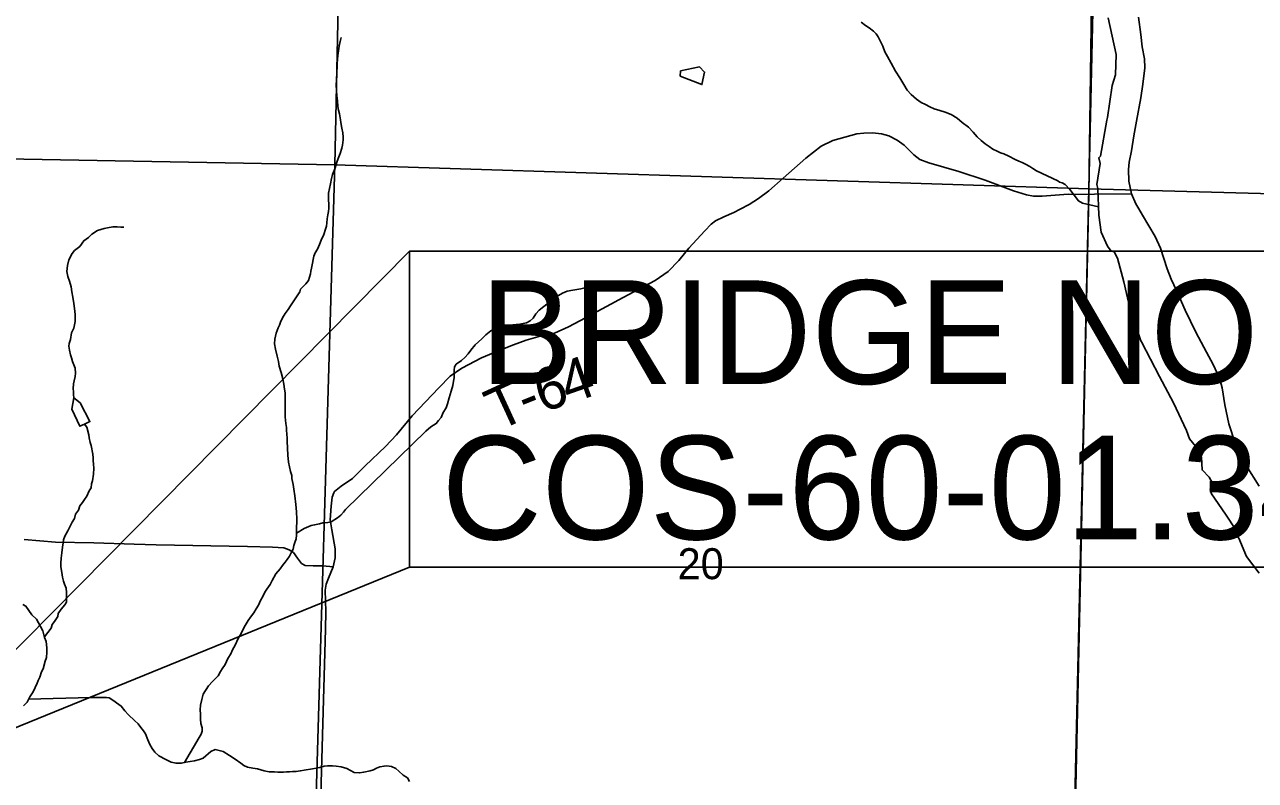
# Model space of a CAD drawing. Extents: x 0 to 34, y 0 to 22.
# Drawn here: x 5.636 to 7.298, y 17.548 to 18.569 of the extents above; entities that cross this region are included whole.
import ezdxf

# ---------------------------------------------------------------- set-up
doc = ezdxf.new("R2010")
doc.units = 0
for name, color, linetype in [('GM_X_Corporation', 7, 'Continuous'), ('GM_X_County_Road', 7, 'Continuous'), ('GM_X_Minor_Lake', 7, 'Continuous'), ('GM_X_Minor_River', 7, 'Continuous'), ('GM_X_Section_Text', 7, 'Continuous'), ('GM_X_Township_Road', 7, 'Continuous'), ('GM_X_Township_Road_Text', 7, 'Continuous'), ('SH_Text', 7, 'Continuous')]:
    doc.layers.add(name, color=color, linetype=linetype)

msp = doc.modelspace()

# ---------------------------------------------------------------- linework, layer by layer
at = {"layer": 'GM_X_Corporation'}
msp.add_lwpolyline([(4.9914, 16.3477), (5.6931, 16.3352), (5.9938, 16.3204), (6.9309, 16.303), (7.0302, 16.2995), (7.0306, 16.367), (7.0337, 16.3927), (7.0334, 16.423), (7.0339, 16.4517), (7.0342, 16.5147), (7.0361, 16.5712), (7.0442, 17.0463), (7.0729, 18.3402), (7.0876, 19.4092), (7.1008, 19.81), (7.1249, 20.7061), (7.1302, 20.9), (2.2795, 20.9)], dxfattribs=at)
for points in [[(8.9, 16.2485), (8.9, 20.9), (7.1302, 20.9), (7.1249, 20.7061), (7.1008, 19.81), (7.0876, 19.4092), (7.0729, 18.3402), (7.0442, 17.0463), (7.0361, 16.5712), (7.0342, 16.5147), (7.0339, 16.4517), (7.0334, 16.423), (7.0337, 16.3927), (7.0306, 16.367), (7.0302, 16.2995), (7.0491, 16.2993), (8.0233, 16.275), (8.785, 16.2515)], [(5.0447, 19.4257), (6.0762, 19.405), (6.0547, 18.3798), (5.0167, 18.3983)], [(6.0762, 19.405), (7.0925, 19.3811), (7.0882, 19.1112), (7.0832, 18.8066), (7.0725, 18.3472), (6.0547, 18.3798)], [(7.0832, 18.8066), (7.5969, 18.8015), (8.1004, 18.7963), (8.0825, 18.3198), (7.0725, 18.3472)], [(5.0167, 18.3983), (6.0547, 18.3798), (6.0244, 17.3604), (4.9971, 17.3675)], [(7.0725, 18.3472), (7.0493, 17.3262), (6.0244, 17.3604), (6.0547, 18.3798)], [(7.0725, 18.3472), (8.0825, 18.3198), (8.0536, 17.3026), (7.0493, 17.3262)]]:
    msp.add_lwpolyline(points, close=True, dxfattribs=at)
at = {"layer": 'GM_X_County_Road'}
for points in [[(6.0524, 17.8366), (6.0383, 17.8378), (6.0255, 17.8378), (6.0147, 17.8382), (6.0098, 17.8409), (6.0044, 17.8482), (5.9988, 17.8558), (5.9928, 17.8597), (5.9856, 17.8622), (5.9707, 17.863), (5.9367, 17.8641), (5.8136, 17.8662), (5.7836, 17.867), (5.7294, 17.8688), (5.6775, 17.8697), (5.6353, 17.8736)], [(6.033, 17.3642), (6.0307, 17.371), (6.0314, 17.3933), (6.0345, 17.4804), (6.0385, 17.6249), (6.0421, 17.7526), (6.0425, 17.7762), (6.0418, 17.8051), (6.0431, 17.8132), (6.0462, 17.8213), (6.0524, 17.8366)]]:
    msp.add_lwpolyline(points, dxfattribs=at)
at = {"layer": 'GM_X_Minor_Lake'}
for points in [[(6.521, 18.4996), (6.5502, 18.4879), (6.5539, 18.505), (6.5471, 18.5118)], [(6.5471, 18.5118), (6.5214, 18.5065), (6.521, 18.4996)], [(5.7024, 18.0647), (5.6994, 18.0495), (5.7104, 18.0264), (5.7169, 18.0295)], [(5.7169, 18.0295), (5.7241, 18.0329), (5.7107, 18.0583), (5.7024, 18.0647)]]:
    msp.add_lwpolyline(points, dxfattribs=at)
at = {"layer": 'GM_X_Minor_River'}
for points in [[(7.3025, 17.828), (7.2855, 17.8504), (7.2754, 17.8754), (7.2735, 17.8777), (7.2712, 17.8868), (7.2573, 17.9077), (7.2385, 17.9354), (7.2366, 17.9411), (7.2396, 17.9498), (7.2351, 17.9578), (7.2257, 17.9676), (7.225, 17.9847), (7.2167, 17.9998), (7.2084, 18.0093), (7.2046, 18.0207), (7.187, 18.0583), (7.1681, 18.0939), (7.144, 18.1406), (7.1429, 18.1417), (7.1283, 18.1842), (7.12, 18.2217), (7.1114, 18.2535), (7.1069, 18.2622), (7.1027, 18.263), (7.0978, 18.2698), (7.0892, 18.2888), (7.0862, 18.3115), (7.0848, 18.3475), (7.0833, 18.3532), (7.0879, 18.3812), (7.086, 18.3892), (7.0883, 18.3911), (7.0971, 18.4399), (7.0979, 18.4437), (7.1044, 18.4868), (7.1086, 18.5012), (7.1094, 18.5285), (7.099, 18.5781)], [(7.0308, 18.3578), (7.0019, 18.3717), (6.997, 18.3747), (6.9932, 18.3774), (6.9871, 18.3804), (6.9829, 18.3827), (6.978, 18.3846), (6.973, 18.3868), (6.9647, 18.3914), (6.9579, 18.3944), (6.9533, 18.3959), (6.9488, 18.3981), (6.9431, 18.4008), (6.9381, 18.4042), (6.9328, 18.408), (6.9275, 18.4125), (6.9218, 18.4174), (6.9165, 18.4239), (6.91, 18.4303), (6.9016, 18.4367), (6.8948, 18.4428), (6.8868, 18.4477), (6.8785, 18.4507), (6.8713, 18.453), (6.8637, 18.4552), (6.858, 18.4579), (6.8523, 18.4609), (6.8462, 18.4639), (6.8398, 18.4681), (6.8326, 18.4745), (6.8276, 18.4805), (6.8227, 18.4881), (6.8173, 18.4972), (6.8116, 18.5063), (6.8059, 18.5169), (6.8009, 18.526), (6.7971, 18.5324), (6.7945, 18.54), (6.7914, 18.5464), (6.7884, 18.5525), (6.7857, 18.5566), (6.7819, 18.5601), (6.7762, 18.5646), (6.7713, 18.568), (6.7652, 18.5725)], [(6.0231, 18.2401), (6.0243, 18.2469), (6.0254, 18.2519), (6.0265, 18.2564), (6.028, 18.2606), (6.0314, 18.2659), (6.034, 18.272), (6.0363, 18.2777), (6.0397, 18.2853), (6.0423, 18.2925), (6.0434, 18.2966), (6.0438, 18.3012), (6.0445, 18.3065), (6.0453, 18.3122), (6.046, 18.3167), (6.0464, 18.3209), (6.0467, 18.3258), (6.046, 18.3334), (6.0463, 18.3414), (6.0489, 18.3539), (6.0504, 18.3611), (6.0515, 18.3664), (6.0545, 18.3744), (6.0579, 18.3846), (6.0602, 18.3903), (6.0621, 18.3949), (6.0643, 18.4021), (6.0651, 18.4062), (6.0658, 18.4134), (6.0658, 18.4172), (6.0654, 18.4229), (6.0642, 18.429), (6.0627, 18.4366), (6.0623, 18.4403), (6.0611, 18.4483), (6.0596, 18.4536), (6.0588, 18.4585), (6.0584, 18.4661), (6.0573, 18.4726), (6.0565, 18.487), (6.0568, 18.4938), (6.0576, 18.5044), (6.0579, 18.5127), (6.0579, 18.5169), (6.0586, 18.5275), (6.0605, 18.54), (6.062, 18.5461), (6.0631, 18.5514)], [(7.0858, 18.323), (7.0643, 18.3279), (7.0587, 18.3309), (7.047, 18.3461), (7.0406, 18.353), (7.0367, 18.3555), (7.035, 18.3558), (7.0331, 18.3564), (7.0308, 18.3578)], [(5.7024, 18.0647), (5.702, 18.0693), (5.7019, 18.0734), (5.7016, 18.0772), (5.7019, 18.084), (5.7027, 18.0878), (5.7042, 18.0935), (5.7045, 18.0981), (5.7041, 18.1049), (5.7007, 18.114), (5.6992, 18.1189), (5.698, 18.1231), (5.6965, 18.1291), (5.6957, 18.1345), (5.6961, 18.1382), (5.6976, 18.1439), (5.699, 18.1527), (5.7021, 18.1591), (5.7032, 18.1637), (5.7039, 18.1678), (5.7039, 18.1773), (5.7031, 18.1856), (5.7023, 18.1921), (5.7008, 18.2008), (5.6996, 18.208), (5.6989, 18.2148), (5.6966, 18.2224), (5.6943, 18.2288), (5.6927, 18.2357), (5.6938, 18.2436), (5.6957, 18.2512), (5.6999, 18.2599), (5.7032, 18.2637), (5.7104, 18.2694), (5.7157, 18.277), (5.7221, 18.2816), (5.7267, 18.2861), (5.7342, 18.2907), (5.7433, 18.2934), (5.7479, 18.2945), (5.7551, 18.2957), (5.7607, 18.2957), (5.7657, 18.2953), (5.7698, 18.2953)], [(5.8518, 17.5722), (5.8716, 17.606), (5.8743, 17.6105), (5.8754, 17.6147), (5.8754, 17.6192), (5.8739, 17.6249), (5.8735, 17.631), (5.8731, 17.6374), (5.873, 17.6435), (5.8734, 17.6499), (5.8749, 17.6572), (5.8771, 17.6644), (5.8839, 17.6757), (5.8896, 17.6818), (5.8971, 17.6894), (5.9005, 17.6951), (5.9024, 17.6989), (5.9066, 17.7046), (5.9103, 17.7126), (5.9141, 17.719), (5.9167, 17.7243), (5.9201, 17.7308), (5.9243, 17.7399), (5.9284, 17.7464), (5.9322, 17.7551), (5.9375, 17.7642), (5.9409, 17.7688), (5.9454, 17.7745), (5.9484, 17.7798), (5.9518, 17.7847), (5.9544, 17.7912), (5.9574, 17.7965), (5.9601, 17.8022), (5.9627, 17.8063), (5.9673, 17.8128), (5.9699, 17.8181), (5.9748, 17.8272), (5.9808, 17.834), (5.9842, 17.8386), (5.9876, 17.8428), (5.9903, 17.8466), (5.9933, 17.8508), (5.9963, 17.8564), (5.9982, 17.8606), (5.9993, 17.8652), (6.0008, 17.8693), (6.0023, 17.8743), (6.0027, 17.8796), (6.003, 17.8853), (6.003, 17.891), (6.0034, 17.8959), (6.0034, 17.9012), (6.0029, 17.9107), (6.0022, 17.9209), (6.0006, 17.9323), (5.9991, 17.9417), (5.9983, 17.9478), (5.9964, 17.9561), (5.9964, 17.9599), (5.9948, 17.9656), (5.9933, 17.9717), (5.9921, 17.9781), (5.991, 17.9876), (5.9906, 17.9971), (5.9905, 18.0065), (5.9901, 18.0103), (5.9893, 18.021), (5.9893, 18.0247), (5.9886, 18.03), (5.9878, 18.0391), (5.9874, 18.0448), (5.9874, 18.052), (5.9877, 18.0581), (5.9877, 18.0717), (5.9869, 18.0767), (5.9857, 18.0835), (5.9846, 18.0907), (5.9823, 18.099), (5.9796, 18.1077), (5.9788, 18.1138), (5.9769, 18.121), (5.9746, 18.1305), (5.9731, 18.1377), (5.9738, 18.1441), (5.9753, 18.1521), (5.9783, 18.1593), (5.9798, 18.1631), (5.9813, 18.1673), (5.9839, 18.1729), (5.9877, 18.1786), (5.9915, 18.184), (5.9949, 18.1893), (5.9994, 18.1961), (6.0028, 18.2014), (6.0073, 18.2079), (6.0084, 18.2117), (6.0156, 18.2189), (6.019, 18.2234), (6.0216, 18.2322), (6.0224, 18.2359), (6.0231, 18.2401)], [(6.0028, 17.8819), (6.0132, 17.8883), (6.0227, 17.8925), (6.0273, 17.8933), (6.0341, 17.8948), (6.0386, 17.896), (6.0454, 17.8967), (6.0496, 17.8975), (6.0583, 17.9028), (6.0628, 17.9066), (6.0662, 17.9104), (6.0692, 17.9142), (6.1777, 18.0198), (6.1841, 18.0255), (6.1917, 18.0301), (6.1947, 18.0343), (6.1981, 18.0381), (6.2011, 18.0449), (6.2052, 18.0513), (6.2067, 18.0567), (6.209, 18.065), (6.2116, 18.0737), (6.2139, 18.0817), (6.215, 18.0874), (6.2157, 18.0919), (6.2157, 18.1022), (6.2161, 18.1067), (6.2187, 18.1105), (6.2259, 18.1154), (6.23, 18.1192), (6.2346, 18.1242), (6.2383, 18.1291), (6.244, 18.1363), (6.2531, 18.1447), (6.2584, 18.15), (6.2652, 18.1553), (6.2716, 18.1587), (6.2792, 18.1614), (6.286, 18.1629), (6.2901, 18.163), (6.3045, 18.1645), (6.3091, 18.1653), (6.3133, 18.1664), (6.3186, 18.1687), (6.3223, 18.1725), (6.3261, 18.1782), (6.3306, 18.1831), (6.3367, 18.1881), (6.3408, 18.1915), (6.345, 18.1953), (6.3499, 18.1991), (6.3567, 18.2033), (6.362, 18.2063), (6.3684, 18.209), (6.376, 18.2101), (6.3866, 18.212), (6.3957, 18.2143), (6.4037, 18.2155), (6.4116, 18.2185), (6.4177, 18.2204)], [(5.6626, 17.7419), (5.6715, 17.7538), (5.673, 17.7587), (5.6764, 17.7629), (5.6805, 17.7697), (5.6813, 17.7735), (5.685, 17.7792), (5.6903, 17.7853), (5.6926, 17.7891), (5.6926, 17.802), (5.6918, 17.808), (5.6895, 17.8133), (5.6883, 17.8171), (5.6872, 17.8228), (5.686, 17.8289), (5.6849, 17.8368), (5.6849, 17.8414), (5.6852, 17.8482), (5.686, 17.8554), (5.6871, 17.863), (5.6878, 17.8691), (5.6885, 17.8732), (5.69, 17.8782), (5.6942, 17.8854), (5.6968, 17.8907), (5.7002, 17.8968), (5.7032, 17.9021), (5.7047, 17.9078), (5.7085, 17.9131), (5.7104, 17.9188), (5.7142, 17.9237), (5.7168, 17.9275), (5.7198, 17.9321), (5.7228, 17.9393), (5.7255, 17.9435), (5.7262, 17.9488), (5.7273, 17.9526), (5.7288, 17.962), (5.7292, 17.97), (5.7288, 17.9753), (5.7284, 17.9802), (5.7284, 17.984), (5.728, 17.9886), (5.7257, 18.0003), (5.7245, 18.0045), (5.723, 18.0109), (5.7226, 18.0147), (5.7199, 18.0253), (5.7169, 18.0295)], [(5.6335, 17.7859), (5.6377, 17.7837), (5.6457, 17.7719), (5.6517, 17.7659), (5.6571, 17.756), (5.6605, 17.75), (5.6628, 17.7413), (5.6651, 17.7356), (5.6659, 17.7272), (5.6659, 17.7215), (5.6655, 17.714), (5.6637, 17.709), (5.661, 17.6988), (5.6588, 17.695), (5.6562, 17.6874), (5.6543, 17.6832), (5.6528, 17.6794), (5.6475, 17.6677), (5.643, 17.6612), (5.6392, 17.6536), (5.6343, 17.6487)], [(5.6412, 17.6577), (5.7248, 17.6599), (5.7339, 17.6599), (5.7385, 17.6603), (5.7423, 17.6603), (5.7464, 17.6599), (5.7502, 17.6595), (5.7563, 17.6558), (5.7601, 17.6527), (5.7662, 17.6486), (5.7711, 17.6421), (5.7761, 17.6368), (5.7844, 17.6289), (5.789, 17.6244), (5.7928, 17.6198), (5.7962, 17.6149), (5.7989, 17.6111), (5.8023, 17.6028), (5.805, 17.5967), (5.808, 17.5914), (5.8118, 17.5861), (5.8171, 17.5812), (5.8263, 17.5763), (5.8338, 17.5729), (5.8403, 17.5714), (5.8475, 17.5714), (5.8535, 17.5726), (5.8653, 17.5745), (5.8721, 17.5764), (5.877, 17.5783), (5.8872, 17.587), (5.8929, 17.5897), (5.9039, 17.5871), (5.9126, 17.5818), (5.9202, 17.5769), (5.9278, 17.5712), (5.932, 17.5682), (5.9366, 17.5659), (5.9438, 17.5648), (5.9502, 17.5637), (5.9593, 17.561), (5.9658, 17.5599), (5.9733, 17.5595), (5.9775, 17.5592), (5.9817, 17.5592), (5.9855, 17.5592), (5.9892, 17.5596), (5.9934, 17.5596), (5.9976, 17.56), (6.0021, 17.56), (6.0082, 17.5611), (6.0131, 17.5619), (6.0245, 17.5638), (6.0343, 17.5657), (6.0404, 17.5673), (6.0449, 17.5677), (6.0517, 17.5677), (6.0567, 17.5673), (6.0631, 17.5666), (6.0711, 17.5643), (6.076, 17.5617), (6.0806, 17.559), (6.0882, 17.5583), (6.0938, 17.5594), (6.1022, 17.5609), (6.1067, 17.5625), (6.1109, 17.5648), (6.1154, 17.5663), (6.1211, 17.5674), (6.1249, 17.5678), (6.1313, 17.5667), (6.137, 17.5641), (6.1412, 17.5606), (6.1469, 17.555), (6.1526, 17.5516), (6.1556, 17.5467)]]:
    msp.add_lwpolyline(points, dxfattribs=at)
at = {"layer": 'GM_X_Township_Road'}
msp.add_line((7.0802, 18.3398), (7.1304, 18.3405), dxfattribs=at)
for points in [[(7.1402, 18.3202), (7.136, 18.3269), (7.1304, 18.3405), (7.1267, 18.3577), (7.1261, 18.3732), (7.1271, 18.3831), (7.1303, 18.3983), (7.1334, 18.4187), (7.1371, 18.4388), (7.1427, 18.4701), (7.1455, 18.4887), (7.1482, 18.5105), (7.1477, 18.5227), (7.1448, 18.5392), (7.1427, 18.5558), (7.1398, 18.5791)], [(6.0535, 17.9364), (6.0542, 17.9384), (6.0633, 17.9454), (6.0785, 17.9557), (6.0958, 17.9731), (6.1229, 17.999), (6.1378, 18.0147), (6.1593, 18.0406), (6.1953, 18.0784), (6.2106, 18.0941), (6.226, 18.1049), (6.2529, 18.1188), (6.2744, 18.1277), (6.2961, 18.1365), (6.3128, 18.143), (6.3317, 18.1481), (6.3513, 18.1521), (6.3701, 18.1608), (6.3933, 18.173), (6.4438, 18.2005), (6.487, 18.2232), (6.5046, 18.2354), (6.5193, 18.2503), (6.5328, 18.2671), (6.5541, 18.2905), (6.5628, 18.2996), (6.5688, 18.3039), (6.5799, 18.3095), (6.5936, 18.3153), (6.6021, 18.3198), (6.6139, 18.3261), (6.6267, 18.3341), (6.6405, 18.3443), (6.66, 18.3618), (6.6906, 18.3887), (6.7111, 18.4047), (6.7272, 18.4123), (6.7593, 18.4214), (6.769, 18.4225), (6.7804, 18.4229), (6.7926, 18.4216), (6.8025, 18.4189), (6.8139, 18.4131), (6.8232, 18.4061), (6.8317, 18.3978), (6.8365, 18.3929), (6.8445, 18.3867), (6.8565, 18.3821), (6.8973, 18.3705), (6.9329, 18.3589), (6.9709, 18.3447), (6.9885, 18.3393), (6.9982, 18.3372), (7.0098, 18.3374), (7.0448, 18.3399), (7.0731, 18.3397), (7.0802, 18.3398)], [(7.3028, 17.9456), (7.285, 17.9733), (7.2763, 17.9893), (7.2701, 18.0035), (7.2618, 18.0296), (7.2564, 18.0555), (7.2527, 18.0784), (7.249, 18.0914), (7.2405, 18.1097), (7.2314, 18.1264), (7.2173, 18.1537), (7.2026, 18.1833), (7.191, 18.2098), (7.184, 18.2251), (7.1785, 18.2391), (7.1695, 18.2671), (7.1623, 18.2828), (7.1453, 18.3118), (7.1402, 18.3202)], [(6.0524, 17.8366), (6.0551, 17.8486), (6.0553, 17.8608), (6.0505, 17.8868), (6.0485, 17.9001), (6.0499, 17.9187), (6.0513, 17.9305), (6.0535, 17.9364)]]:
    msp.add_lwpolyline(points, dxfattribs=at)
at = {"layer": 'SH_Text'}
for points in [[(5.4492, 17.5486), (6.1555, 17.8363), (6.1555, 18.2631)], [(6.1555, 18.2631), (7.474, 18.2631), (7.474, 17.8363), (6.1555, 17.8363)]]:
    msp.add_lwpolyline(points, close=True, dxfattribs=at)

# ---------------------------------------------------------------- texts
at = {"layer": 'GM_X_Section_Text'}
msp.add_text('20', height=0.04186, rotation=0, dxfattribs=at).set_placement((6.5175, 17.8199))
at = {"layer": 'GM_X_Township_Road_Text'}
for s, rotation, p in [('4', 19.2895, (6.3702, 18.0559)), ('6', 16.1255, (6.3333, 18.0451)), ('T', 24.6883, (6.2751, 18.0194)), ('-', 21.8753, (6.3131, 18.0369))]:
    msp.add_text(s, height=0.0568, rotation=rotation, dxfattribs=at).set_placement(p)
at = {"layer": 'SH_Text'}
for s, p in [(' BRIDGE NO', (6.199, 18.0836)), ('COS-60-01.34', (6.199, 17.8736))]:
    msp.add_text(s, height=0.14, dxfattribs=at).set_placement(p)

doc.saveas('drawing.dxf')
